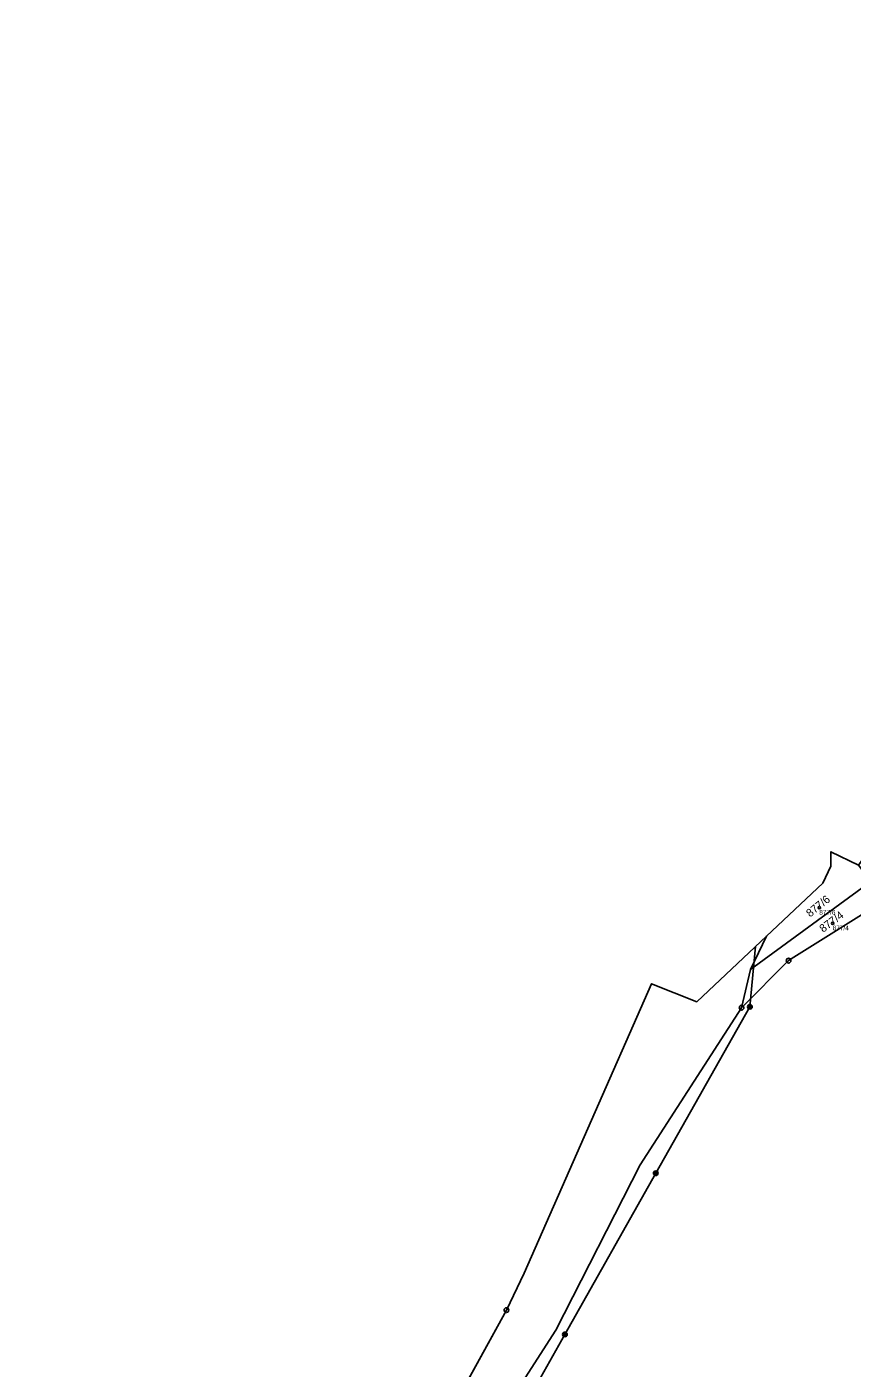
# Model space of a CAD drawing. Extents: x -603967 to -594699, y -1179315 to -1165625.
# Drawn here: x -597944.8 to -597769.4, y -1171940.7 to -1171655.7 of the extents above; entities that cross this region are included whole.
import ezdxf

# ---------------------------------------------------------------- set-up
doc = ezdxf.new("R2010")
doc.units = 0
for name, color, linetype in [('Definiční body', 7, 'Continuous'), ('Hranice parcel', 7, 'Continuous'), ('Parcelní čísla', 7, 'Continuous'), ('Polygon ku', 7, 'Continuous'), ('Polygon parcely', 7, 'Continuous'), ('Poz předměty', 7, 'Continuous'), ('Značky bodu BP', 7, 'Continuous')]:
    doc.layers.add(name, color=color, linetype=linetype)

msp = doc.modelspace()

# ---------------------------------------------------------------- linework, layer by layer
at = {"layer": 'Definiční body'}
for centre in [(-597776.42, -1171842.81994), (-597773.58, -1171846.13994)]:
    msp.add_circle(centre, 0.25, dxfattribs=at)
at = {"layer": 'Hranice parcel'}
for p, q in [((-597768.06, -1171833.78), (-597773.93, -1171830.93)), ((-597765.42, -1171837.23), (-597790.99, -1171855.96)), ((-597787.61, -1171848.88), (-597775.64, -1171837.64)), ((-597802.44, -1171862.82), (-597787.61, -1171848.88)), ((-597790.99, -1171855.96), (-597787.61, -1171848.88)), ((-597792.93, -1171864.07), (-597790.99, -1171855.96)), ((-597839.12, -1171920.5), (-597812.06, -1171858.99)), ((-597812.06, -1171858.99), (-597802.44, -1171862.82)), ((-597842.88, -1171928.34), (-597839.12, -1171920.5)), ((-597873.95, -1171984.89), (-597842.88, -1171928.34))]:
    msp.add_line(p, q, dxfattribs=at)
for points in [[(-597792.93, -1171864.07), (-597782.92, -1171854.08), (-597761.77, -1171840.83), (-597752.08, -1171833.17), (-597735.39, -1171817.89)], [(-597773.93, -1171830.93), (-597773.98, -1171833.97), (-597775.64, -1171837.64)], [(-597840.14, -1171944.71), (-597832.37, -1171932.6), (-597814.46, -1171897.49), (-597792.93, -1171864.07)]]:
    msp.add_lwpolyline(points, dxfattribs=at)
at = {"layer": 'Polygon ku'}
msp.add_lwpolyline([(-597749.58, -1171629.77), (-597671.18, -1171720.11), (-597667.8, -1171722.99), (-597700.88, -1171751.58), (-597739.99, -1171795.85), (-597743.31, -1171805.03), (-597764.43, -1171828.86), (-597768.06, -1171833.78), (-597773.93, -1171830.93), (-597773.98, -1171833.97), (-597775.64, -1171837.64), (-597787.61, -1171848.88), (-597802.44, -1171862.82), (-597812.06, -1171858.99), (-597839.12, -1171920.5), (-597842.88, -1171928.34), (-597873.95, -1171984.89)], dxfattribs=at)
at = {"layer": 'Polygon parcely'}
for points in [[(-597761.77, -1171840.83), (-597752.08, -1171833.17), (-597735.39, -1171817.89), (-597718.97, -1171800.46), (-597709.56, -1171790.47), (-597753.96, -1171831.23), (-597764.1, -1171838.95), (-597765.42, -1171837.23), (-597790.99, -1171855.96), (-597792.93, -1171864.07), (-597782.92, -1171854.08)], [(-597840.14, -1171944.71), (-597740.6, -1171996.76), (-597667.54, -1171852.18), (-597735.39, -1171817.89), (-597752.08, -1171833.17), (-597761.77, -1171840.83), (-597782.92, -1171854.08), (-597792.93, -1171864.07), (-597814.46, -1171897.49), (-597832.37, -1171932.6)], [(-597773.93, -1171830.93), (-597773.98, -1171833.97), (-597775.64, -1171837.64), (-597787.61, -1171848.88), (-597790.99, -1171855.96), (-597765.42, -1171837.23), (-597768.06, -1171833.78)], [(-597944.79, -1172109.68), (-597942.17, -1172109.1), (-597936.55, -1172110.75), (-597935.86, -1172106.88), (-597935.06, -1172105.51), (-597928.4, -1172094.84), (-597919.12, -1172079.89), (-597910.08, -1172065.46), (-597904.62, -1172053.54), (-597903.46, -1172051.4), (-597901.05, -1172047.15), (-597899.15, -1172043.97), (-597840.14, -1171944.71), (-597832.37, -1171932.6), (-597814.46, -1171897.49), (-597792.93, -1171864.07), (-597790.99, -1171855.96), (-597787.61, -1171848.88), (-597802.44, -1171862.82), (-597812.06, -1171858.99), (-597839.12, -1171920.5), (-597842.88, -1171928.34), (-597873.95, -1171984.89), (-597943.43, -1172107.29)]]:
    msp.add_lwpolyline(points, close=True, dxfattribs=at)
at = {"layer": 'Poz předměty'}
for p, q in [((-597789.94, -1171851.07), (-597791.15, -1171863.89)), ((-597791.15, -1171863.89), (-597811.16, -1171899.26)), ((-597811.16, -1171899.26), (-597830.44, -1171933.51)), ((-597830.44, -1171933.51), (-597850.51, -1171968.93))]:
    msp.add_line(p, q, dxfattribs=at)
for centre, radius in [((-597791.15343, -1171863.88988), 0.5), ((-597791.15343, -1171863.88988), 0.4), ((-597791.15343, -1171863.88988), 0.3), ((-597791.15343, -1171863.88988), 0.2), ((-597791.15343, -1171863.88988), 0.1), ((-597811.16343, -1171899.25988), 0.5), ((-597811.16343, -1171899.25988), 0.4), ((-597811.16343, -1171899.25988), 0.3), ((-597811.16343, -1171899.25988), 0.2), ((-597811.16343, -1171899.25988), 0.1), ((-597830.44343, -1171933.50988), 0.5), ((-597830.44343, -1171933.50988), 0.4), ((-597830.44343, -1171933.50988), 0.3), ((-597830.44343, -1171933.50988), 0.2), ((-597830.44343, -1171933.50988), 0.1)]:
    msp.add_circle(centre, radius, dxfattribs=at)
at = {"layer": 'Značky bodu BP'}
for centre, radius in [((-597782.92, -1171854.07988), 0.5), ((-597782.92, -1171854.07988), 0.0303), ((-597792.93, -1171864.06988), 0.5), ((-597792.93, -1171864.06988), 0.0303), ((-597842.88, -1171928.33988), 0.5), ((-597842.88, -1171928.33988), 0.0303)]:
    msp.add_circle(centre, radius, dxfattribs=at)

# ---------------------------------------------------------------- texts
at = {"layer": 'Definiční body'}
for s, p in [('877/6', (-597776.42, -1171844.309)), ('877/4', (-597773.58, -1171847.629))]:
    msp.add_text(s, height=0.999996, dxfattribs=at).set_placement(p)
at = {"layer": 'Parcelní čísla'}
for s, rotation, p in [('877/6', 39, (-597778.356, -1171844.935)), ('877/4', 37, (-597775.589, -1171848.186))]:
    msp.add_text(s, height=1.699998, rotation=rotation, dxfattribs=at).set_placement(p)

doc.saveas('drawing.dxf')
